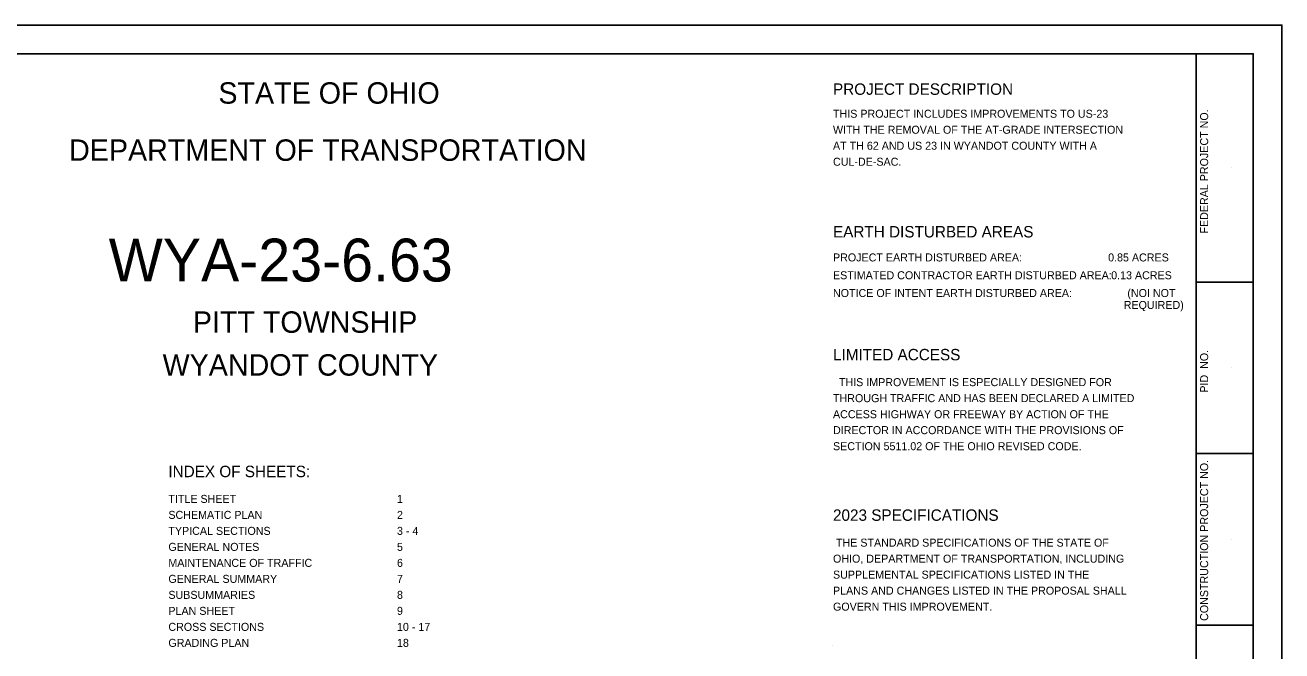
# Model space of a CAD drawing. Extents: x -17 to 88, y -5 to 22.
# Drawn here: x 12.01 to 34, y 11.05 to 22 of the extents above; entities that cross this region are included whole.
import ezdxf

# ---------------------------------------------------------------- set-up
doc = ezdxf.new("R2010")
doc.units = 0
for name, color, linetype in [('SH_Border', 7, 'Continuous'), ('SH_Cut_Line', 7, 'Continuous'), ('SH_Data', 7, 'Continuous'), ('TX_P_10', 7, 'Continuous')]:
    doc.layers.add(name, color=color, linetype=linetype)

msp = doc.modelspace()

# ---------------------------------------------------------------- linework, layer by layer
at = {"layer": 'SH_Border'}
for p, q in [((32.5, 0.5), (32.5, 21.5)), ((32.5, 17.5), (33.5, 17.5)), ((32.5, 14.5), (33.5, 14.5)), ((32.5, 11.5), (33.5, 11.5))]:
    msp.add_line(p, q, dxfattribs=at)
msp.add_lwpolyline([(2, 21.5), (33.5, 21.5), (33.5, 0.5), (2, 0.5)], close=True, dxfattribs=at)
at = {"layer": 'SH_Cut_Line'}
msp.add_lwpolyline([(0, 0), (34, 0), (34, 22), (0, 22)], close=True, dxfattribs=at)
at = {"layer": 'SH_Data'}
for p, q in [((33.125, 19.5), (33.125, 19.5)), ((33.125, 16), (33.125, 16)), ((33.125, 13), (33.125, 13)), ((26.146, 11.14), (26.146, 11.14))]:
    msp.add_line(p, q, dxfattribs=at)

# ---------------------------------------------------------------- texts
for s, height, p in [('STATE OF OHIO', 0.375, (15.392, 20.625)), ('PROJECT DESCRIPTION', 0.2, (26.146, 20.78)), ('DEPARTMENT OF TRANSPORTATION', 0.375, (12.78, 19.625)), ('EARTH DISTURBED AREAS', 0.2, (26.146, 18.284)), ('WYA-23-6.63', 0.75, (13.473, 17.513)), ('PROJECT EARTH DISTURBED AREA:', 0.14, (26.146, 17.864)), ('0.85 ACRES', 0.14, (30.96, 17.864)), ('ESTIMATED CONTRACTOR EARTH DISTURBED AREA:', 0.14, (26.146, 17.552)), ('0.13 ACRES', 0.14, (31.013, 17.552)), ('NOTICE OF INTENT EARTH DISTURBED AREA:', 0.14, (26.146, 17.241)), ('(NOI NOT', 0.14, (31.297, 17.241)), ('REQUIRED)', 0.14, (31.233, 17.032)), ('PITT TOWNSHIP', 0.375, (14.945, 16.615)), ('LIMITED ACCESS', 0.2, (26.146, 16.133)), ('WYANDOT COUNTY', 0.375, (14.416, 15.865)), ('  THIS IMPROVEMENT IS ESPECIALLY DESIGNED FOR', 0.14, (26.146, 15.681)), ('THROUGH TRAFFIC AND HAS BEEN DECLARED A LIMITED', 0.14, (26.146, 15.401)), ('ACCESS HIGHWAY OR FREEWAY BY ACTION OF THE', 0.14, (26.146, 15.12)), ('DIRECTOR IN ACCORDANCE WITH THE PROVISIONS OF', 0.14, (26.146, 14.841)), ('SECTION 5511.02 OF THE OHIO REVISED CODE.', 0.14, (26.146, 14.56)), ('INDEX OF SHEETS:', 0.2, (14.517, 14.088)), ('TITLE SHEET', 0.14, (14.517, 13.638)), ('1', 0.14, (18.517, 13.638)), ('SCHEMATIC PLAN', 0.14, (14.517, 13.358)), ('2', 0.14, (18.517, 13.358)), ('2023 SPECIFICATIONS', 0.2, (26.146, 13.324)), ('TYPICAL SECTIONS', 0.14, (14.517, 13.078)), ('3 - 4', 0.14, (18.517, 13.078)), (' THE STANDARD SPECIFICATIONS OF THE STATE OF', 0.14, (26.146, 12.872)), ('GENERAL NOTES', 0.14, (14.517, 12.798)), ('5', 0.14, (18.517, 12.798)), ('MAINTENANCE OF TRAFFIC', 0.14, (14.517, 12.518)), ('6', 0.14, (18.517, 12.518)), ('OHIO, DEPARTMENT OF TRANSPORTATION, INCLUDING', 0.14, (26.146, 12.592)), ('GENERAL SUMMARY', 0.14, (14.517, 12.238)), ('7', 0.14, (18.517, 12.238)), ('SUPPLEMENTAL SPECIFICATIONS LISTED IN THE', 0.14, (26.146, 12.312)), ('SUBSUMMARIES', 0.14, (14.517, 11.958)), ('8', 0.14, (18.517, 11.958)), ('PLANS AND CHANGES LISTED IN THE PROPOSAL SHALL', 0.14, (26.146, 12.032)), ('GOVERN THIS IMPROVEMENT.', 0.14, (26.146, 11.752)), ('PLAN SHEET', 0.14, (14.517, 11.678)), ('9', 0.14, (18.517, 11.678)), ('CROSS SECTIONS', 0.14, (14.517, 11.398)), ('10 - 17', 0.14, (18.517, 11.398)), ('GRADING PLAN', 0.14, (14.517, 11.118)), ('18', 0.14, (18.517, 11.118))]:
    msp.add_text(s, height=height, dxfattribs=at).set_placement(p)
for s, p in [('FEDERAL PROJECT NO.', (32.71, 18.352)), ('PID  NO.', (32.71, 15.567)), ('CONSTRUCTION PROJECT NO.', (32.71, 11.572))]:
    msp.add_text(s, height=0.14, rotation=90, dxfattribs=at).set_placement(p)
at = {"layer": 'TX_P_10'}
for s, p in [('THIS PROJECT INCLUDES IMPROVEMENTS TO US-23 ', (26.146, 20.379)), ('WITH THE REMOVAL OF THE AT-GRADE INTERSECTION ', (26.146, 20.099)), ('AT TH 62 AND US 23 IN WYANDOT COUNTY WITH A ', (26.146, 19.819)), ('CUL-DE-SAC.', (26.146, 19.539))]:
    msp.add_text(s, height=0.14, dxfattribs=at).set_placement(p)

doc.saveas('drawing.dxf')
